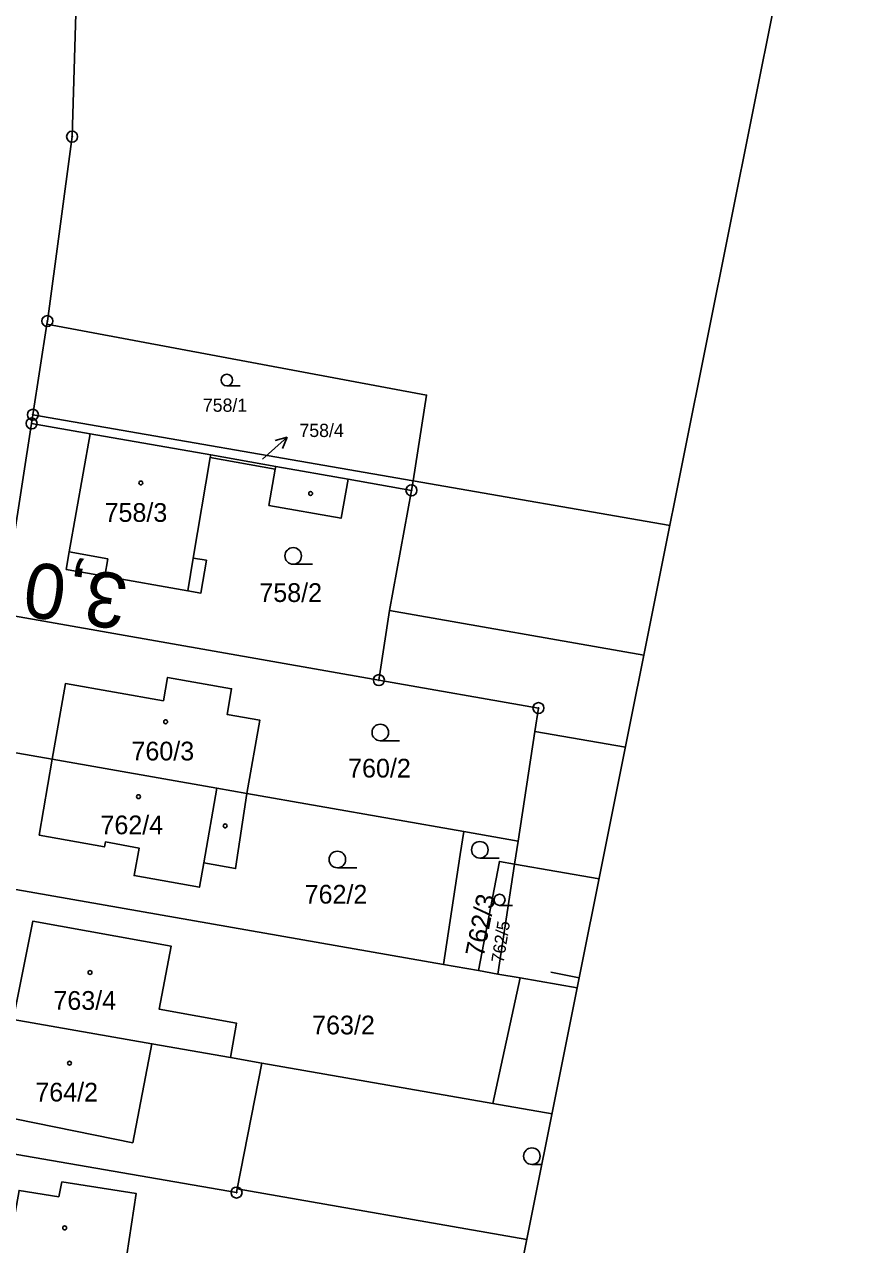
# Model space of a CAD drawing. Extents: x -548552 to -543113, y -1131925 to -1123599.
# Drawn here: x -547591.7 to -547515.1, y -1128652.9 to -1128542.1 of the extents above; entities that cross this region are included whole.
import ezdxf

# ---------------------------------------------------------------- set-up
doc = ezdxf.new("R2010")
doc.units = 0
for name, color, linetype in [('Hranice parcel', 7, 'Continuous'), ('Parcelní čísla', 7, 'Continuous'), ('Pop  PČ popisy', 7, 'Continuous'), ('Profile', 7, 'Continuous'), ('STANIČENÍ', 7, 'Continuous'), ('Vnitřní kresba', 7, 'Continuous'), ('Značky bodu BP', 7, 'Continuous'), ('Značky budov', 7, 'Continuous'), ('Značky kultur', 7, 'Continuous')]:
    doc.layers.add(name, color=color, linetype=linetype)

msp = doc.modelspace()

# ---------------------------------------------------------------- linework, layer by layer
at = {"layer": 'Hranice parcel'}
for p, q in [((-547589.64, -1128569.36), (-547590.9, -1128577.57)), ((-547590.9, -1128577.57), (-547591.02, -1128578.36)), ((-547590.9, -1128577.57), (-547556.42, -1128583.56)), ((-547585.7, -1128579.29), (-547591.02, -1128578.36)), ((-547556.56, -1128584.43), (-547562.31, -1128583.41)), ((-547556.42, -1128583.56), (-547556.56, -1128584.43)), ((-547556.42, -1128583.56), (-547533.11, -1128587.61)), ((-547556.56, -1128584.43), (-547558.54, -1128595.34)), ((-547593.69, -1128595.65), (-547559.52, -1128601.65)), ((-547559.52, -1128601.65), (-547558.54, -1128595.34)), ((-547558.54, -1128595.34), (-547535.47, -1128599.39)), ((-547545.36, -1128606.31), (-547546.89, -1128616.26)), ((-547545.36, -1128606.31), (-547537.15, -1128607.75)), ((-547595.56, -1128607.71), (-547589.15, -1128608.83)), ((-547571.48, -1128611.94), (-547551.81, -1128615.39)), ((-547551.81, -1128615.39), (-547546.89, -1128616.26)), ((-547546.89, -1128616.26), (-547547.21, -1128618.35)), ((-547547.21, -1128618.35), (-547548.73, -1128628.32)), ((-547547.21, -1128618.35), (-547539.54, -1128619.69)), ((-547597.42, -1128619.77), (-547553.66, -1128627.45)), ((-547553.66, -1128627.45), (-547550.48, -1128628.01)), ((-547548.73, -1128628.32), (-547550.48, -1128628.01)), ((-547546.71, -1128628.67), (-547549.19, -1128640.06)), ((-547548.73, -1128628.32), (-547546.71, -1128628.67)), ((-547546.71, -1128628.67), (-547541.52, -1128629.58)), ((-547572.97, -1128635.9), (-547570.12, -1128636.4)), ((-547570.12, -1128636.4), (-547572.36, -1128647.81)), ((-547570.12, -1128636.4), (-547549.19, -1128640.06)), ((-547549.19, -1128640.06), (-547543.81, -1128641)), ((-547572.36, -1128647.81), (-547546.1, -1128652.4))]:
    msp.add_line(p, q, dxfattribs=at)
for points in [[(-547584.79, -1128503.81), (-547586.2, -1128513.79), (-547587.34, -1128552.33), (-547589.59, -1128569.07), (-547589.64, -1128569.36)], [(-547589.64, -1128569.36), (-547555.19, -1128575.79), (-547556.42, -1128583.56)], [(-547591.02, -1128578.36), (-547592.72, -1128589.33), (-547593.69, -1128595.65)], [(-547562.31, -1128583.41), (-547562.94, -1128586.96), (-547569.49, -1128585.8), (-547568.91, -1128582.51), (-547574.81, -1128581.46), (-547576.35, -1128590.58), (-547575.16, -1128590.78), (-547575.66, -1128593.75), (-547576.84, -1128593.54), (-547584.38, -1128592.22), (-547587.87, -1128591.6), (-547587.6, -1128590.02), (-547585.7, -1128579.29)], [(-547562.31, -1128583.41), (-547568.86, -1128582.26), (-547574.77, -1128581.22), (-547585.7, -1128579.29)], [(-547589.15, -1128608.83), (-547587.95, -1128601.97), (-547579.06, -1128603.53), (-547578.69, -1128601.41), (-547572.88, -1128602.43), (-547573.29, -1128604.77), (-547570.31, -1128605.29), (-547571.48, -1128611.94)], [(-547559.52, -1128601.65), (-547545.04, -1128604.19), (-547545.36, -1128606.31)], [(-547571.48, -1128611.94), (-547572.52, -1128618.76), (-547575.39, -1128618.22), (-547575.8, -1128620.44), (-547581.72, -1128619.39), (-547581.27, -1128616.89), (-547584.32, -1128616.33), (-547584.41, -1128616.78), (-547590.33, -1128615.71), (-547589.15, -1128608.83)], [(-547589.15, -1128608.83), (-547574.23, -1128611.46), (-547571.48, -1128611.94)], [(-547553.66, -1128627.45), (-547552.13, -1128617.49), (-547551.81, -1128615.39)], [(-547550.48, -1128628.01), (-547548.59, -1128618.11), (-547547.21, -1128618.35)], [(-547592.69, -1128632.45), (-547590.92, -1128623.53), (-547578.37, -1128625.79), (-547579.46, -1128631.51), (-547572.44, -1128632.77), (-547572.97, -1128635.9)], [(-547592.69, -1128632.45), (-547580.1, -1128634.65), (-547572.97, -1128635.9)], [(-547601.99, -1128643.03), (-547572.43, -1128648.15), (-547572.36, -1128647.81)], [(-547579.29, -1128654.27), (-547580.08, -1128659.32), (-547583.18, -1128658.83), (-547593.79, -1128657.16), (-547592.16, -1128647.96), (-547588.56, -1128648.53), (-547588.27, -1128647.18), (-547581.52, -1128648.24), (-547582.39, -1128653.79), (-547579.29, -1128654.27)]]:
    msp.add_lwpolyline(points, dxfattribs=at)
at = {"layer": 'Pop  PČ popisy'}
for p, q in [((-547570.08, -1128581.61), (-547567.85, -1128579.6)), ((-547567.85, -1128579.6), (-547568.93, -1128579.9)), ((-547567.85, -1128579.6), (-547568.26, -1128580.64))]:
    msp.add_line(p, q, dxfattribs=at)
at = {"layer": 'Profile'}
for p, q in [((-547515.1, -1128497.74), (-547533.93, -1128591.68)), ((-547533.93, -1128591.68), (-547557.04, -1128706.96)), ((-547541.34, -1128628.67), (-547543.93, -1128628.15))]:
    msp.add_line(p, q, dxfattribs=at)
at = {"layer": 'Vnitřní kresba'}
for p, q in [((-547574.81, -1128581.46), (-547574.77, -1128581.22)), ((-547568.91, -1128582.51), (-547568.86, -1128582.26)), ((-547587.6, -1128590.02), (-547584.1, -1128590.64)), ((-547584.1, -1128590.64), (-547584.38, -1128592.22)), ((-547576.35, -1128590.58), (-547576.84, -1128593.54)), ((-547574.23, -1128611.46), (-547575.39, -1128618.22)), ((-547581.85, -1128643.64), (-547580.1, -1128634.65)), ((-547594.38, -1128641.1), (-547581.85, -1128643.64))]:
    msp.add_line(p, q, dxfattribs=at)
at = {"layer": 'Značky bodu BP'}
for centre, radius in [((-547587.34, -1128552.33), 0.5), ((-547587.34, -1128552.33), 0.0303), ((-547589.59, -1128569.07), 0.5), ((-547589.59, -1128569.07), 0.0303), ((-547591.02, -1128578.36), 0.5), ((-547590.9, -1128577.57), 0.5), ((-547590.9, -1128577.57), 0.0303), ((-547591.02, -1128578.36), 0.0303), ((-547556.56, -1128584.43), 0.5), ((-547556.56, -1128584.43), 0.0303), ((-547559.52, -1128601.65), 0.5), ((-547559.52, -1128601.65), 0.0303), ((-547545.04, -1128604.19), 0.5), ((-547545.04, -1128604.19), 0.0303), ((-547572.43, -1128648.15), 0.5), ((-547572.43, -1128648.15), 0.0303)]:
    msp.add_circle(centre, radius, dxfattribs=at)
at = {"layer": 'Značky budov'}
for centre in [(-547581.11, -1128583.76), (-547565.71, -1128584.72), (-547578.86, -1128605.43), (-547581.32, -1128612.23), (-547573.46, -1128614.88), (-547585.72, -1128628.18), (-547587.58, -1128636.41), (-547588.02, -1128651.36)]:
    msp.add_circle(centre, 0.175, dxfattribs=at)
at = {"layer": 'Značky kultur'}
for p, q in [((-547573.31, -1128574.95), (-547572.09, -1128574.95)), ((-547567.29, -1128591.13), (-547565.54, -1128591.13)), ((-547559.39, -1128607.15), (-547557.64, -1128607.15)), ((-547550.36, -1128617.8), (-547548.61, -1128617.8)), ((-547563.28, -1128618.68), (-547561.53, -1128618.68)), ((-547548.57, -1128622.1), (-547547.4, -1128622.1)), ((-547545.64, -1128645.6), (-547544.73, -1128645.6))]:
    msp.add_line(p, q, dxfattribs=at)
for centre, radius in [((-547573.31, -1128574.42), 0.525), ((-547567.29, -1128590.38), 0.75), ((-547559.39, -1128606.4), 0.75), ((-547550.36, -1128617.05), 0.75), ((-547563.28, -1128617.93), 0.75), ((-547548.57, -1128621.59), 0.502), ((-547545.64, -1128644.85), 0.75)]:
    msp.add_circle(centre, radius, dxfattribs=at)

# ---------------------------------------------------------------- texts
at = {"layer": 'Parcelní čísla'}
for s, height, p in [('758/1', 1.2, (-547575.48, -1128577.3)), ('758/4', 1.2, (-547566.72, -1128579.59)), ('758/3', 1.7, (-547584.4, -1128587.29)), ('758/2', 1.7, (-547570.36, -1128594.56)), ('760/3', 1.7, (-547581.96, -1128608.94)), ('760/2', 1.7, (-547562.31, -1128610.49)), ('762/4', 1.7, (-547584.77, -1128615.64)), ('762/2', 1.7, (-547566.25, -1128621.93)), ('763/4', 1.7, (-547589.04, -1128631.57)), ('763/2', 1.7, (-547565.57, -1128633.8)), ('764/2', 1.7, (-547590.68, -1128639.89))]:
    msp.add_text(s, height=height, dxfattribs=at).set_placement(p)
for s, height, rotation, p in [('762/3', 1.7, 79, (-547550.02, -1128626.84)), ('762/5', 1.139, 81, (-547548.21, -1128627.37))]:
    msp.add_text(s, height=height, rotation=rotation, dxfattribs=at).set_placement(p)
at = {"layer": 'STANIČENÍ'}
msp.add_text('3,0', height=5, rotation=171.9617, dxfattribs=at).set_placement((-547582.09, -1128592.16))

doc.saveas('drawing.dxf')
